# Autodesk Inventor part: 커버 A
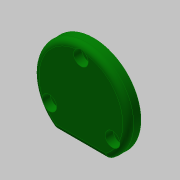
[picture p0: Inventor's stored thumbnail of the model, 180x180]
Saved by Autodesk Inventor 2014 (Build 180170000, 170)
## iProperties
Created: 2020-04
Part Number: 커버 A
Material: 알루미늄 6061
Document SubType Name: Modeling
Designer: mduedu
Density: 2.71 g/cm^3
Mass: 30.8954 g
Surface Area: 61.0157 cm^2
Volume: 11.4005 cm^3
Appearance: Dark Green
Author: mduedu
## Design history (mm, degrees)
sketch "스케치1"
  geometry: C1 r 26 at (0, 0); 1 further point
  constraints: 1 centre point, 1 coincident
  dimensions: "d0" = 52 diameter of C1
extrude "돌출1" new body sketch "스케치1" distance "d1" = 7; taper "d2" = 0 deg
sketch "스케치2"
  geometry: L1 (-14.62, -21.5)-(14.62, -21.5); A1 r 26 centre (0, 0) between (-14.62, -21.5) and (14.62, -21.5) reference; 1 further point
  constraints: 2 end point, 2 point on circle, 1 horizontal
  dimensions: "d3" = 21.5 distance from line of L1 point (0, 0)
extrude "돌출2" cut sketch "스케치2" stored distance "d4" = 7; taper "d5" = 0 deg
fillet "모깎기1" dims "d6" = 3
fillet "모깎기2" dims "d7" = 3
sketch "스케치3" dims "d8" = 40
  geometry: 3 further points
  constraints: 2 vertical alignment, 1 coincident, 2 other
hole "구멍1" sketch "스케치3" at (0, 20) diameter "d9" = 4.5; stored, may be unused: countersink angle "d13" = 90 deg, drill point angle "d15" = 118 deg; dims "d10" = 6, "d11" = 8, "d12" = 4.4, "d14" = 8
sketch "스케치4"
  geometry: C1 r 16 at (0, 0); 1 further point
  constraints: 1 centre point, 1 coincident
  dimensions: "d19" = 32 diameter of C1
extrude "돌출3" join sketch "스케치4" distance "d20" = 3; taper "d21" = 0 deg
sketch "스케치5"
  geometry: C1 r 14 at (0, 0); 1 further point
  constraints: 1 centre point, 1 coincident
  dimensions: "d22" = 28 diameter of C1
extrude "돌출4" cut sketch "스케치5" distance "d23" = 7; taper "d24" = 0 deg
fillet "모깎기3" dims "d25" = 3
chamfer "모따기1" distance "d26" = 0.5; stored, may be unused: second distance "d27" = 2, angle "d28" = 45 deg
node "솔리드1"
pattern_circular "원형 패턴1" dims angle "d17" = 360 deg
node "투영된 루프1"
